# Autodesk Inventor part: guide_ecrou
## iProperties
Created: 2004-05
Part Number: guide_ecrou
Material: Par défaut
Document SubType Name: Modélisation
Designer: Danielc
Author: David YERLE
Control State: 0
Master: False
Checked Out: False
Shininess: 20.0
Length Units: 11269
Angle Units: 11279
Time Units: 11290
Mass Units: 11283
Length Display Precision: 3
Angle Display Precision: 2
Density: 0.0
Volumn: 0.0
Area: 0.0
PropertySet Name: Model Information
Author: Danielc
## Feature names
1. Extrusion1
2. Perçage1 [Hole]
3. Perçage2 [Hole]
4. Extrusion2
5. Congé1 [Fillet]
